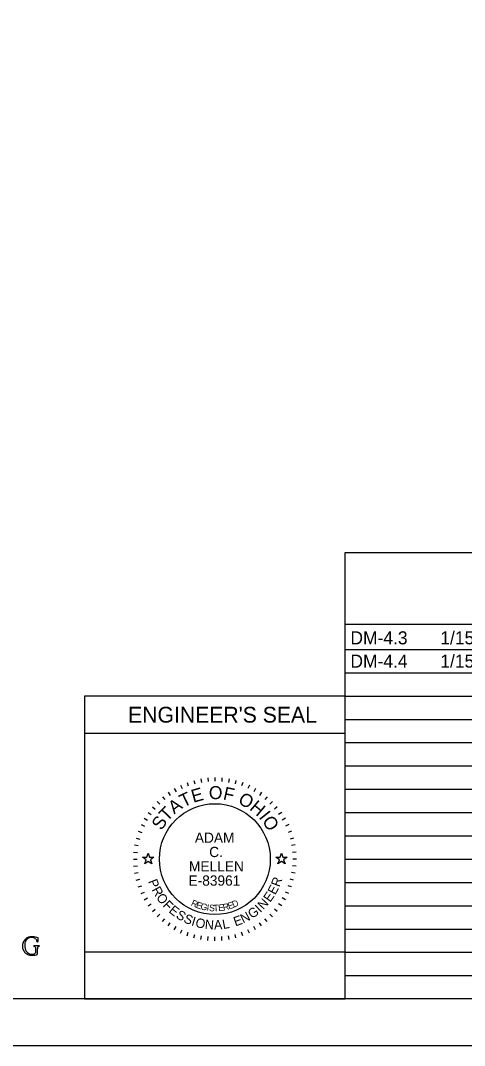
# Model space of a CAD drawing. Extents: x 0 to 34, y 0 to 22.
# Drawn here: x 6.66 to 11.43, y 0 to 11 of the extents above; entities that cross this region are included whole.
import ezdxf

# ---------------------------------------------------------------- set-up
doc = ezdxf.new("R2010")
doc.units = 0
for name, color, linetype in [('Default', 7, 'Continuous'), ('SH_Border', 7, 'Continuous'), ('SH_Cut_Line', 7, 'Continuous'), ('SH_Data', 7, 'Continuous'), ('SH_Text', 7, 'Continuous')]:
    doc.layers.add(name, color=color, linetype=linetype)

msp = doc.modelspace()

# ---------------------------------------------------------------- linework, layer by layer
at = {"layer": 'Default'}
for points in [[(7.974, 2.02), (8.021, 2.02), (8.035, 2.065), (8.049, 2.02), (8.096, 2.02), (8.058, 1.992), (8.073, 1.948), (8.035, 1.975), (7.997, 1.948), (8.012, 1.992)], [(9.404, 2.02), (9.451, 2.02), (9.465, 2.065), (9.479, 2.02), (9.526, 2.02), (9.488, 1.992), (9.503, 1.948), (9.465, 1.975), (9.427, 1.948), (9.442, 1.992)]]:
    msp.add_lwpolyline(points, close=True, dxfattribs=at)
at = {"layer": 'SH_Border'}
msp.add_lwpolyline([(1.5, 21.5), (33.5, 21.5), (33.5, 0.5), (1.5, 0.5)], close=True, dxfattribs=at)
at = {"layer": 'SH_Cut_Line'}
msp.add_lwpolyline([(0, 0), (34, 0), (34, 22), (0, 22)], close=True, dxfattribs=at)
at = {"layer": 'SH_Data'}
for p, q in [((10.15, 5.292), (23.6, 5.292)), ((10.15, 0.5), (10.15, 5.292)), ((10.15, 4.521), (23.6, 4.521)), ((10.15, 4.25), (23.6, 4.25)), ((10.15, 4), (23.6, 4)), ((10.15, 3.75), (7.35, 3.75)), ((7.35, 3.75), (7.35, 0.5)), ((10.15, 3.75), (23.6, 3.75)), ((10.15, 0.5), (10.15, 3.75)), ((10.15, 3.5), (23.6, 3.5)), ((10.15, 3.35), (7.35, 3.35)), ((10.15, 3.25), (23.6, 3.25)), ((10.15, 3), (23.6, 3)), ((8.598, 2.862), (8.605, 2.822)), ((8.674, 2.872), (8.677, 2.832)), ((8.75, 2.875), (8.75, 2.835)), ((8.826, 2.872), (8.823, 2.832)), ((8.902, 2.862), (8.895, 2.822)), ((8.313, 2.758), (8.333, 2.723)), ((8.38, 2.793), (8.397, 2.757)), ((8.451, 2.822), (8.464, 2.785)), ((8.524, 2.845), (8.534, 2.807)), ((8.976, 2.845), (8.966, 2.807)), ((9.049, 2.822), (9.036, 2.785)), ((9.12, 2.793), (9.103, 2.757)), ((9.187, 2.758), (9.167, 2.723)), ((10.15, 2.75), (23.6, 2.75)), ((8.188, 2.67), (8.213, 2.64)), ((8.248, 2.717), (8.271, 2.684)), ((9.252, 2.717), (9.229, 2.684)), ((9.312, 2.67), (9.287, 2.64)), ((8.08, 2.562), (8.11, 2.537)), ((8.131, 2.619), (8.16, 2.59)), ((9.369, 2.619), (9.34, 2.59)), ((9.42, 2.562), (9.39, 2.537)), ((7.992, 2.438), (8.027, 2.418)), ((8.033, 2.502), (8.066, 2.479)), ((9.467, 2.502), (9.434, 2.479)), ((9.508, 2.438), (9.473, 2.418)), ((10.15, 2.5), (23.6, 2.5)), ((7.957, 2.37), (7.993, 2.353)), ((9.543, 2.37), (9.507, 2.353)), ((7.905, 2.226), (7.943, 2.216)), ((7.928, 2.299), (7.965, 2.286)), ((9.572, 2.299), (9.535, 2.286)), ((9.595, 2.226), (9.557, 2.216)), ((10.15, 2.25), (23.6, 2.25)), ((7.888, 2.152), (7.928, 2.145)), ((9.612, 2.152), (9.572, 2.145)), ((7.875, 2), (7.915, 2)), ((7.878, 2.076), (7.918, 2.073)), ((9.622, 2.076), (9.582, 2.073)), ((9.625, 2), (9.585, 2)), ((10.15, 2), (23.6, 2)), ((7.878, 1.924), (7.918, 1.927)), ((9.622, 1.924), (9.582, 1.927)), ((7.888, 1.848), (7.928, 1.855)), ((7.905, 1.774), (7.943, 1.784)), ((9.595, 1.774), (9.557, 1.784)), ((9.612, 1.848), (9.572, 1.855)), ((7.928, 1.701), (7.965, 1.714)), ((9.572, 1.701), (9.535, 1.714)), ((10.15, 1.75), (23.6, 1.75)), ((7.957, 1.63), (7.993, 1.647)), ((7.992, 1.563), (8.027, 1.583)), ((9.508, 1.563), (9.473, 1.583)), ((9.543, 1.63), (9.507, 1.647)), ((8.033, 1.498), (8.066, 1.521)), ((8.08, 1.438), (8.11, 1.463)), ((9.42, 1.438), (9.39, 1.463)), ((9.467, 1.498), (9.434, 1.521)), ((10.15, 1.5), (23.6, 1.5)), ((8.131, 1.381), (8.16, 1.41)), ((8.188, 1.33), (8.213, 1.36)), ((9.312, 1.33), (9.287, 1.36)), ((9.369, 1.381), (9.34, 1.41)), ((8.248, 1.283), (8.271, 1.316)), ((8.313, 1.242), (8.333, 1.277)), ((8.38, 1.207), (8.397, 1.243)), ((8.451, 1.178), (8.464, 1.215)), ((9.049, 1.178), (9.036, 1.215)), ((9.12, 1.207), (9.103, 1.243)), ((9.187, 1.242), (9.167, 1.277)), ((9.252, 1.283), (9.229, 1.316)), ((10.15, 1.25), (23.6, 1.25)), ((8.524, 1.155), (8.534, 1.193)), ((8.598, 1.138), (8.605, 1.178)), ((8.674, 1.128), (8.677, 1.168)), ((8.75, 1.125), (8.75, 1.165)), ((8.826, 1.128), (8.823, 1.168)), ((8.902, 1.138), (8.895, 1.178)), ((8.976, 1.155), (8.966, 1.193)), ((10.15, 1), (23.6, 1)), ((10.15, 0.75), (23.6, 0.75)), ((10.15, 0.5), (7.35, 0.5))]:
    msp.add_line(p, q, dxfattribs=at)
msp.add_lwpolyline([(10.15, 0.5), (10.15, 1), (7.35, 1), (7.35, 0.5)], close=True, dxfattribs=at)
msp.add_circle((8.75, 2), 0.595, dxfattribs=at)
at = {"layer": 'SH_Text'}
for p, q in [((6.864, 1.068), (6.806, 1.068)), ((6.823, 1.05), (6.823, 0.994)), ((6.847, 0.988), (6.847, 1.036))]:
    msp.add_line(p, q, dxfattribs=at)
for centre, radius, start, end in [((6.754, 1.077), 0.0685, 158.442, 167.8164), ((6.798, 1.06), 0.116, 157.2066, 158.442), ((6.798, 1.06), 0.116, 135.2994, 157.2066), ((6.85, 1.072), 0.142, 167.8795, 178.2857), ((6.817, 1.079), 0.108, 165.5071, 167.8795), ((6.781, 1.088), 0.0714, 147.5385, 165.5071), ((6.777, 1.08), 0.0867, 107.613, 135.2994), ((6.781, 1.088), 0.0714, 116.7026, 147.5385), ((6.776, 1.099), 0.0589, 93.5922, 116.7026), ((6.779, 1.076), 0.0916, 90.0889, 107.613), ((6.783, 0.986), 0.172, 87.6816, 93.5922), ((6.779, 0.913), 0.254, 85.6243, 90.0889), ((6.788, 1.108), 0.0509, 59.809, 87.6816), ((6.78, 0.924), 0.243, 73.3259, 85.6243), ((6.754, 1.05), 0.117, 52.0865, 59.809), ((6.803, 1.112), 0.0384, 2.9119, 52.0865), ((6.846, 1.115), 0.00447, 182.9119, 350.1479), ((6.848, 1.152), 0.00494, 1.0594, 73.3259), ((6.65, 1.148), 0.203, 350.1479, 1.0594), ((6.824, 1.062), 0.141, 167.8164, 176.8679), ((6.775, 1.064), 0.0913, 176.8679, 187.4835), ((6.763, 1.063), 0.0789, 187.4835, 199.5864), ((6.83, 1.087), 0.151, 199.5864, 208.6065), ((6.769, 1.054), 0.0815, 208.6065, 229.3453), ((6.806, 1.073), 0.0979, 178.2857, 190.5998), ((6.941, 1.098), 0.235, 190.5998, 194.5022), ((6.792, 1.06), 0.0818, 194.5022, 227.8932), ((6.791, 1.079), 0.115, 229.3453, 237.7571), ((6.788, 1.055), 0.0755, 227.8932, 268.7516), ((6.806, 1.066), 0.00203, 90, 277.32), ((6.808, 1.05), 0.0146, 0, 97.32), ((6.815, 0.994), 0.00829, 293.6665, 0), ((7.006, 1.036), 0.159, 172.0456, 180), ((6.854, 1.057), 0.00585, 114.8736, 172.0456), ((6.862, 1.04), 0.0242, 95.8947, 114.8736), ((6.877, 0.891), 0.174, 94.3316, 95.8947), ((6.864, 1.067), 0.00179, 274.3316, 90), ((6.767, 1.04), 0.0686, 237.7571, 254.2366), ((6.784, 1.103), 0.134, 254.2366, 269.1033), ((6.787, 1.274), 0.306, 269.1033, 278.6618), ((6.788, 1.055), 0.075, 268.7516, 293.6665), ((6.831, 0.988), 0.016, 278.6618, 0)]:
    msp.add_arc(centre, radius, start, end, dxfattribs=at)

# ---------------------------------------------------------------- texts
at = {"layer": 'SH_Data'}
for s, height, p in [("ENGINEER'S SEAL", 0.17, (7.818, 3.465)), ('ADAM', 0.11, (8.535, 2.175)), ('C.', 0.11, (8.689, 2.022)), ('MELLEN', 0.11, (8.472, 1.868)), ('E-83961', 0.11, (8.467, 1.715))]:
    msp.add_text(s, height=height, dxfattribs=at).set_placement(p)
for s, height, rotation, p in [('E', 0.14, 15.7571, (8.518, 2.604)), ('O', 0.14, 359.7812, (8.685, 2.644)), ('F', 0.14, 347.4362, (8.831, 2.642)), ('T', 0.14, 25.7167, (8.412, 2.552)), ('O', 0.14, 332.2586, (8.99, 2.602)), ('T', 0.14, 46.4344, (8.238, 2.396)), ('A', 0.14, 36.4747, (8.313, 2.478)), ('H', 0.14, 319.9136, (9.113, 2.536)), ('S', 0.14, 57.1924, (8.178, 2.301)), ('I', 0.14, 308.367, (9.216, 2.448)), ('O', 0.14, 303.1491, (9.252, 2.409)), ('P', 0.1, 291.494, (8.032, 1.762)), ('R', 0.1, 69.2322, (9.442, 1.695)), ('R', 0.1, 298.7311, (8.069, 1.672)), ('E', 0.1, 54.758, (9.343, 1.531)), ('E', 0.1, 61.9951, (9.398, 1.61)), ('O', 0.1, 306.4666, (8.115, 1.588)), ('F', 0.1, 314.7068, (8.184, 1.498)), ('R', 0.07, 334.487, (8.487, 1.505)), ('E', 0.07, 341.04, (8.541, 1.48)), ('E', 0.07, 17.6836, (8.9, 1.46)), ('D', 0.07, 23.3052, (8.951, 1.477)), ('N', 0.1, 47.0224, (9.27, 1.451)), ('E', 0.1, 321.4393, (8.248, 1.435)), ('S', 0.1, 328.6764, (8.324, 1.375)), ('G', 0.07, 347.4752, (8.591, 1.462)), ('I', 0.07, 353.7858, (8.659, 1.447)), ('S', 0.07, 356.8926, (8.686, 1.443)), ('T', 0.07, 3.0061, (8.736, 1.439)), ('E', 0.07, 6.0117, (8.789, 1.441)), ('R', 0.07, 11.9184, (8.842, 1.447)), ('N', 0.1, 27.3113, (9.054, 1.308)), ('G', 0.1, 35.0469, (9.148, 1.357)), ('I', 0.1, 43.287, (9.237, 1.421)), ('S', 0.1, 335.9134, (8.406, 1.327)), ('I', 0.1, 343.1505, (8.491, 1.29)), ('O', 0.1, 346.8859, (8.534, 1.275)), ('N', 0.1, 355.1261, (8.639, 1.252)), ('A', 0.1, 2.8617, (8.742, 1.244)), ('L', 0.1, 10.0987, (8.839, 1.249)), ('E', 0.1, 20.0742, (8.971, 1.277))]:
    msp.add_text(s, height=height, rotation=rotation, dxfattribs=at).set_placement(p)
at = {"layer": 'SH_Text'}
for s, p in [('DM-4.3', (10.205, 4.305)), ('1/15/16', (11.17, 4.305)), ('DM-4.4', (10.205, 4.055)), ('1/15/16', (11.17, 4.055))]:
    msp.add_text(s, height=0.14, dxfattribs=at).set_placement(p)

doc.saveas('drawing.dxf')
